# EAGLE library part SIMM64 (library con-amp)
AMP connector
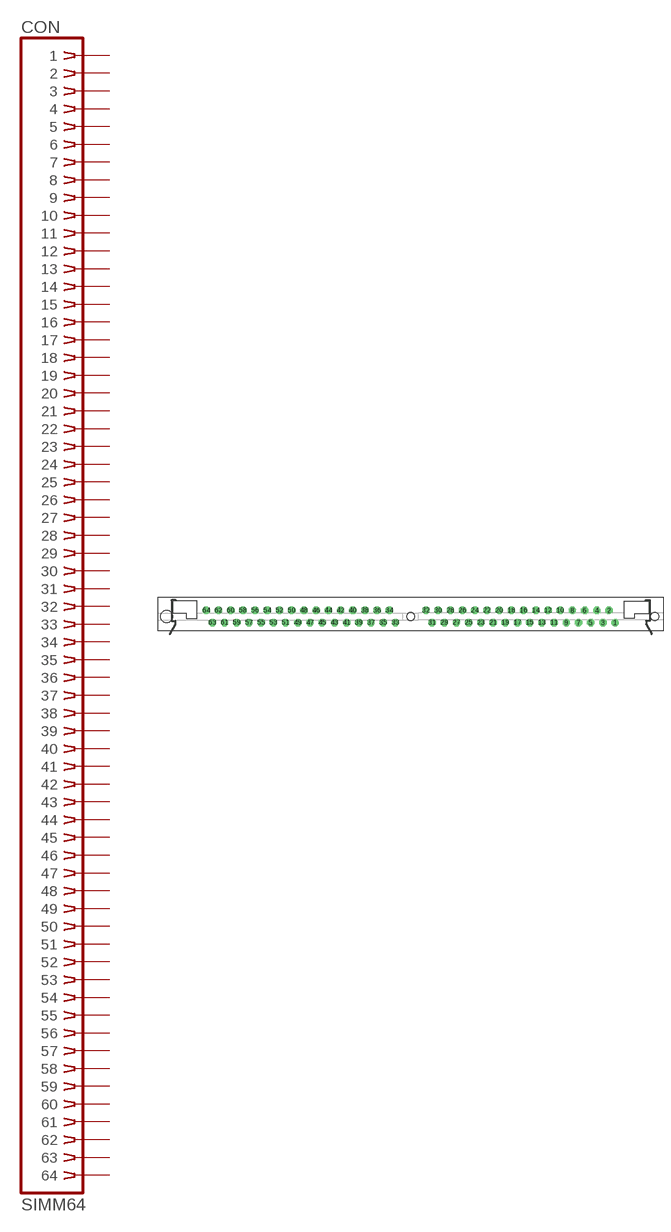
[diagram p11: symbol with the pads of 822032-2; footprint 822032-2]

Designator prefix CON

## SIMM64 (OC_FARNELL: unknown; OC_NEWARK: unknown)  [822032-2]
1  1  pas
2  2  pas
3  3  pas
4  4  pas
5  5  pas
6  6  pas
7  7  pas
8  8  pas
9  9  pas
10  10  pas
11  11  pas
12  12  pas
13  13  pas
14  14  pas
15  15  pas
16  16  pas
17  17  pas
18  18  pas
19  19  pas
20  20  pas
21  21  pas
22  22  pas
23  23  pas
24  24  pas
25  25  pas
26  26  pas
27  27  pas
28  28  pas
29  29  pas
30  30  pas
31  31  pas
32  32  pas
33  33  pas
34  34  pas
35  35  pas
36  36  pas
37  37  pas
38  38  pas
39  39  pas
40  40  pas
41  41  pas
42  42  pas
43  43  pas
44  44  pas
45  45  pas
46  46  pas
47  47  pas
48  48  pas
49  49  pas
50  50  pas
51  51  pas
52  52  pas
53  53  pas
54  54  pas
55  55  pas
56  56  pas
57  57  pas
58  58  pas
59  59  pas
60  60  pas
61  61  pas
62  62  pas
63  63  pas
64  64  pas

## Footprint 822032-2 (pad centres in mm)
SIMM Socket
drill 1.016 round: 1 42.545,-1.27
drill 1.016 octagon: 2 41.275,1.27; 3 40.005,-1.27; 4 38.735,1.27; 5 37.465,-1.27; 6 36.195,1.27; 7 34.925,-1.27; 8 33.655,1.27; 9 32.385,-1.27; 10 31.115,1.27; 11 29.845,-1.27; 12 28.575,1.27; 13 27.305,-1.27; 14 26.035,1.27; 15 24.765,-1.27; 16 23.495,1.27; 17 22.225,-1.27; 18 20.955,1.27; 19 19.685,-1.27; 20 18.415,1.27; 21 17.145,-1.27; 22 15.875,1.27; 23 14.605,-1.27; 24 13.335,1.27; 25 12.065,-1.27; 26 10.795,1.27; 27 9.525,-1.27; 28 8.255,1.27; 29 6.985,-1.27; 30 5.715,1.27; 31 4.445,-1.27; 32 3.175,1.27; 33 -3.175,-1.27; 34 -4.445,1.27; 35 -5.715,-1.27; 36 -6.985,1.27; 37 -8.255,-1.27; 38 -9.525,1.27; 39 -10.795,-1.27; 40 -12.065,1.27; 41 -13.335,-1.27; 42 -14.605,1.27; 43 -15.875,-1.27; 44 -17.145,1.27; 45 -18.415,-1.27; 46 -19.685,1.27; 47 -20.955,-1.27; 48 -22.225,1.27; 49 -23.495,-1.27; 50 -24.765,1.27; 51 -26.035,-1.27; 52 -27.305,1.27; 53 -28.575,-1.27; 54 -29.845,1.27; 55 -31.115,-1.27; 56 -32.385,1.27; 57 -33.655,-1.27; 58 -34.925,1.27; 59 -36.195,-1.27; 60 -37.465,1.27; 61 -38.735,-1.27; 62 -40.005,1.27; 63 -41.275,-1.27; 64 -42.545,1.27
hole 2.438 at -50.8,0
hole 1.626 at 50.8,0
hole 1.626 at 0,0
